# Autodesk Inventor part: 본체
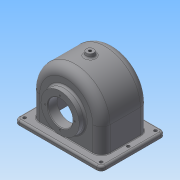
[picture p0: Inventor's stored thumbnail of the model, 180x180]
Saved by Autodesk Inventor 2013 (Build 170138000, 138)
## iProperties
Created: 2015-09
Part Number: 본체
Material: 일반
Document SubType Name: Modeling
Designer: Administrator
Density: 1 g/cm^3
Author: Administrator
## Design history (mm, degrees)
sketch "스케치1"
  geometry: L1 (-52, 70)-(52, 70); L2 (52, 70)-(52, -70); L3 (52, -70)-(-52, -70); L4 (-52, -70)-(-52, 70); 3 further points
  constraints: 8 end point, 2 midpoint, 2 parallel, 1 horizontal, 1 horizontal alignment, 1 perpendicular, 1 vertical alignment
  dimensions: "d0" = 104 distance of L1.start L1.end; "d2" = 140 distance of L3.end L1.start
extrude "돌출1" new body sketch "스케치1" distance "d3" = 7; taper "d4" = 0 deg
sketch "스케치2" dims "d100" = 3
  geometry: L1 (70, 7)-(-70, 7) reference; L2 (-57, 7)-(-57, 47); L3 (57, 47)-(57, 7); L4 (-70, 0)-(70, 0) reference; A1 r 57 centre (0, 47) between (57, 47) and (-57, 47); 2 further points
  constraints: 4 end point, 2 perpendicular, 2 point on circle, 2 point on line, 2 tangent, 1 centre point, 1 midpoint, 1 vertical alignment
  dimensions: "d5" = 47 distance from line of L4 A1.centre; "d7" = 57 radius of A1
extrude "돌출2" join sketch "스케치2" stored distance "d8" = 77; taper "d9" = 0 deg
sketch "스케치7"
  geometry: L1 (-57, 7)-(-57, 47) reference; L2 (57, 47)-(57, 7) reference; L3 (-51, 7)-(-51, 47); L4 (51, 47)-(51, 7); L5 (-51, 7)-(-51, -13.982); L6 (-51, -13.982)-(51, -13.982); L7 (51, -13.982)-(51, 7); A1 r 57 centre (0, 47) between (57, 47) and (-57, 47) reference; A2 r 51 centre (0, 47) between (51, 47) and (-51, 47); 1 further point
  constraints: 10 end point, 2 point on circle, 1 centre point, 1 collinear, 1 parallel, 1 perpendicular, 2 other
  dimensions: "d21" = 6 distance between parallel lines of L1 L3
extrude "돌출5" cut sketch "스케치7" stored distance "d22" = 67; taper "d23" = 0 deg
sketch "스케치15"
  geometry: C1 r 31 at (47, 0); A1 r 57 centre (47, 0) between (47, -57) and (47, 57) reference; 1 further point
  constraints: 1 centre point, 1 coincident
  dimensions: "d52" = 62 diameter of C1
extrude "돌출7" join sketch "스케치15" distance "d54" = 10; taper "d55" = 0 deg
sketch "스케치18"
  geometry: L1 (33.5, 0)-(-33.5, 0) reference; L2 (-49.949, 47)-(14.472, 47); L3 (-33.5, 98)-(-33.5, 47) reference; L4 (-33.5, 86.747)-(-19.5, 75); L5 (-19.5, 75)-(-19.5, 47); L6 (-33.5, 86.747)-(-33.5, 47); L7 (-33.5, 47)-(-19.5, 47); 1 further point
  constraints: 10 end point, 2 parallel, 2 point on line, 1 perpendicular
  dimensions: "d70" = 47 distance between parallel lines of L1 L2; "d71" = 56 diameter of L4.end L2; "d72" = 50 deg angle of L4 L5; "d73" = 14 distance between parallel lines of L3 L5
revolve "회전3" sketch "스케치18" stored, may be unused: angle "d74" = 90 deg
sketch "스케치19"
  geometry: L1 (-33.5, 86.747)-(-19.5, 75) reference; L2 (-38.5, 84.416)-(-33.237, 80); L3 (-38.5, 104)-(-38.5, 47) reference; L4 (-38.5, 47)-(-19.5, 47); L5 (-19.5, 19)-(-19.5, 75) reference; L6 (-33.237, 80)-(-35.5, 80); L7 (-35.5, 80)-(-35.5, 47); L8 (-38.5, 84.416)-(-38.5, 47); L9 (-35.5, 47)-(-38.5, 47); 1 further point
  constraints: 12 end point, 3 perpendicular, 2 parallel, 2 point on line, 1 collinear, 1 midpoint
  dimensions: "d75" = 5 distance between parallel lines of L2 L1; "d76" = 3 distance between parallel lines of L3 L7; "d77" = 66 diameter of L6 L4
revolve "회전4" sketch "스케치19" stored, may be unused: angle "d78" = 90 deg
fillet "모깎기2" dims "d79" = 0.5
sketch "스케치20" dims "d80" = 56
  geometry: C1 r 33 at (0, 0) reference; 3 further points
  constraints: 2 vertical alignment, 1 coincident, 2 other
hole "구멍2" sketch "스케치20" at (0, 28) diameter "d82" = 2.459; stored, may be unused: countersink angle "d86" = 90 deg, drill point angle "d88" = 118 deg; dims "d83" = 7, "d84" = 4, "d85" = 2, "d87" = 9
hole "구멍1" diameter "d58" = 40; stored, may be unused: countersink angle "d62" = 90 deg, drill point angle "d64" = 0 deg; dims "d59" = 6, "d60" = 4, "d61" = 2, "d63" = 30, "d92" = 10, "d93" = 10
node "작업 평면1"
sketch "스케치21"
  geometry: C1 r 6 at (0, 0); 1 further point
  constraints: 1 centre point, 1 coincident
  dimensions: "d95" = 12 diameter of C1
extrude "돌출9" join sketch "스케치21" stored distance "d97" = 14; taper "d98" = 10 deg
fillet "모깎기4" dims "d100" = 3
hole "구멍3" diameter "d103" = 4.459; stored, may be unused: countersink angle "d107" = 90 deg, drill point angle "d109" = 118 deg; dims "d101" = 10, "d102" = 10, "d104" = 28, "d105" = 4, "d106" = 2, "d108" = 30
sketch "스케치22" dims "d110" = 48
  geometry: C1 r 20 at (0, 0) reference; 3 further points
  constraints: 2 vertical alignment, 1 coincident, 2 other
hole "구멍4" sketch "스케치22" at (0, 24) diameter "d112" = 2.621; stored, may be unused: countersink angle "d116" = 90 deg, drill point angle "d118" = 118 deg; dims "d113" = 6, "d114" = 4, "d115" = 2, "d117" = 8
sketch "스케치23"
  geometry: L1 (-13.5, 47)-(90.5, 47) reference; L2 (62.364, 13.623)-(14.636, 13.623); L3 (14.636, 13.623)-(14.636, 20.377); L4 (14.636, 20.377)-(62.364, 20.377); L5 (62.364, 20.377)-(62.364, 13.623); 5 further points
  constraints: 3 midpoint, 2 vertical alignment, 1 horizontal alignment, 2 other
  dimensions: "d122" = 30 distance from line of L1 point (38.5, 17)
feature "엠보싱1" sketch "스케치23" dims "d0" = 104, "d2" = 140, "d123" = 0.5, "d124" = 0
fillet "모깎기5" dims "d125" = 14
fillet "모깎기6" dims "d126" = 3
fillet "모깎기7" dims "d127" = 9
chamfer "모따기1" distance "d128" = 1; stored, may be unused: second distance "d129" = 2, angle "d130" = 45 deg
sketch "스케치24"
  geometry: L1 (-38.5, -43)-(-38.5, 43) reference; L2 (-24.5, 57)-(24.5, 57) reference; L3 (38.5, 43)-(38.5, -43) reference; L4 (24.5, -57)-(-24.5, -57) reference; L5 (52, 70)-(-52, 70) reference; L6 (-52, 70)-(-52, -70) reference; L7 (-52, -70)-(52, -70) reference; L8 (52, -70)-(52, 70) reference; A1 r 14 centre (-24.5, 43) between (-24.5, 57) and (-38.5, 43) reference; A2 r 14 centre (24.5, 43) between (38.5, 43) and (24.5, 57) reference; A3 r 14 centre (24.5, -43) between (24.5, -57) and (38.5, -43) reference; A4 r 14 centre (-24.5, -43) between (-38.5, -43) and (-24.5, -57) reference; 7 further points
  constraints: 4 horizontal alignment, 4 vertical alignment
  dimensions: "d136" = 8 distance from line of L8 point (44, -62); "d137" = 8 distance from line of L7 point (44, -62); "d138" = 124 distance of point (44, 62) point (44, -62); "d139" = 88 distance of point (-44, -62) point (44, -62)
hole "구멍5" sketch "스케치24" at (44, -62), (-44, -62), (-44, 62), (44, 62), (0, 62), (0, -62) diameter "d140" = 5; stored, may be unused: countersink angle "d144" = 90 deg, drill point angle "d146" = 118 deg; dims "d141" = 6, "d142" = 4, "d143" = 2, "d145" = 8
fillet "모깎기8" dims "d147" = 1
fillet "모깎기9" dims "d148" = 3
fillet "모깎기10" dims "d149" = 7
fillet "모깎기11" dims "d150" = 3
node "솔리드1"
pattern_circular "원형 패턴1" dims angle "d90" = 360 deg
pattern_circular "원형 패턴2" dims angle "d120" = 360 deg
node "투영된 루프2"
